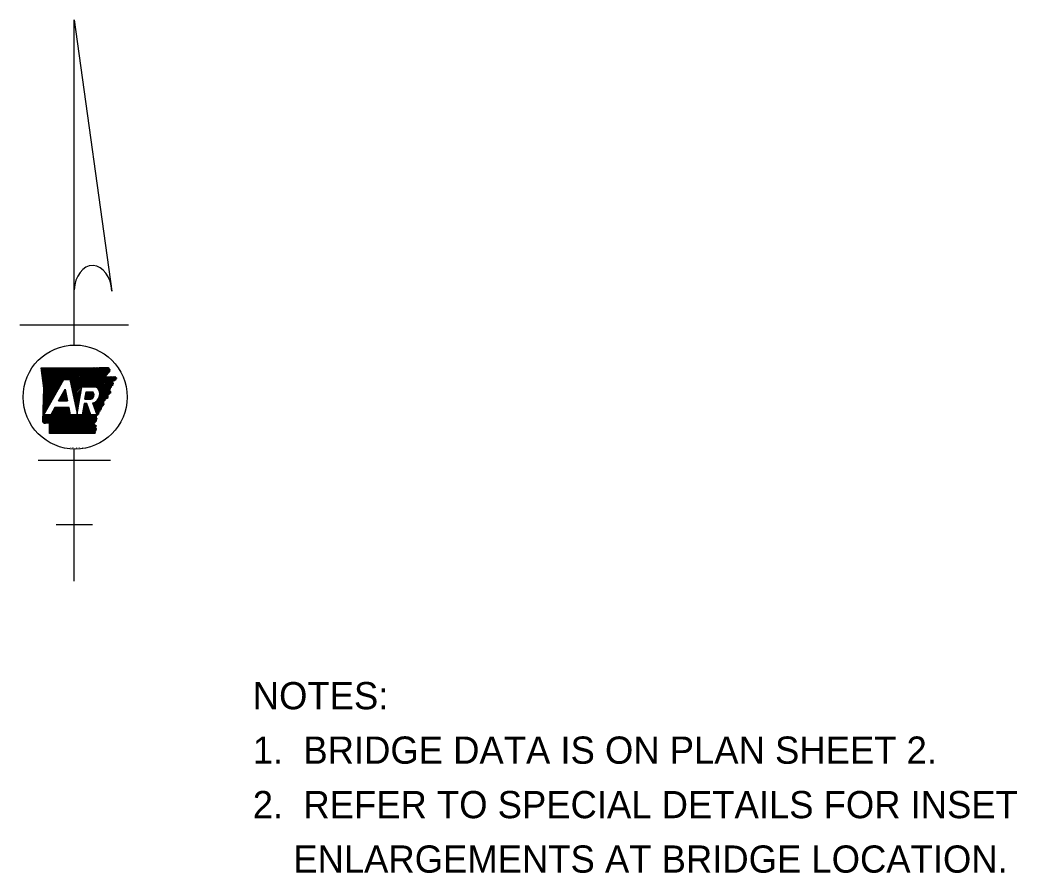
# Model space of a CAD drawing. Extents: x -35254 to 17396, y -8913 to 11592.
# Drawn here: x -7186 to -2354, y -2282 to 1853 of the extents above; entities that cross this region are included whole.
import ezdxf

# ---------------------------------------------------------------- set-up
doc = ezdxf.new("R2010")
doc.units = 0
doc.layers.add('3', color=7, linetype='Continuous')
doc.layers.add('R_Annotation', color=7, linetype='Continuous')

msp = doc.modelspace()

# ---------------------------------------------------------------- linework, layer by layer
at = {"layer": 'R_Annotation'}
for p, q in [((-6922.6, 1853.5), (-6740.7, 539.3)), ((-6922.6, 277.6), (-6922.6, 1853.5)), ((-7185.8, 375), (-6659.5, 375)), ((-7082.2, 164.7), (-7080.1, 166.9)), ((-7081.5, 158.5), (-7073.1, 166.9)), ((-7080.7, 152.3), (-7066.1, 166.9)), ((-7079.9, 146.1), (-7059.2, 166.9)), ((-7079.1, 139.9), (-7052.2, 166.9)), ((-7078.4, 133.7), (-7045.2, 166.9)), ((-7077.6, 127.5), (-7038.3, 166.9)), ((-7076.8, 121.3), (-7031.3, 166.8)), ((-7076.1, 115.2), (-7024.4, 166.8)), ((-7075.3, 109), (-7017.4, 166.8)), ((-7074.5, 102.8), (-7010.4, 166.8)), ((-7073.7, 96.6), (-7003.5, 166.8)), ((-7073, 90.4), (-6996.5, 166.8)), ((-7072.2, 84.2), (-6989.6, 166.8)), ((-7072, 14.8), (-6919.8, 167)), ((-7071.7, 22), (-6926.7, 166.9)), ((-7071.5, 29.2), (-6933.7, 166.9)), ((-7071.4, 78), (-6982.6, 166.8)), ((-7071.2, 36.4), (-6940.7, 166.9)), ((-7071, 43.6), (-6947.7, 166.9)), ((-7070.8, 50.8), (-6954.7, 166.9)), ((-7070.7, 71.8), (-6975.6, 166.8)), ((-7070.5, 58), (-6961.6, 166.9)), ((-7070.3, 65.2), (-6968.6, 166.9)), ((-6968.5, 111.2), (-6912.8, 167)), ((-6961.6, 111.2), (-6905.8, 167)), ((-6954.6, 111.2), (-6898.8, 167)), ((-6947.6, 111.2), (-6891.7, 167.2)), ((-6943.3, 108.6), (-6884.6, 167.3)), ((-6942.1, 102.9), (-6877.5, 167.4)), ((-6940.8, 97.1), (-6870.5, 167.5)), ((-6939.6, 91.4), (-6863.4, 167.6)), ((-6938.4, 85.7), (-6856.3, 167.7)), ((-6937.1, 79.9), (-6849.2, 167.8)), ((-6935.9, 74.2), (-6842.2, 167.9)), ((-6934.7, 68.4), (-6835.1, 168)), ((-6933.5, 62.7), (-6828, 168.1)), ((-6932.2, 57), (-6820.9, 168.3)), ((-6931, 51.2), (-6813.9, 168.4)), ((-6929.8, 45.5), (-6806.8, 168.5)), ((-6928.6, 39.7), (-6799.7, 168.6)), ((-6927.3, 34), (-6792.6, 168.8)), ((-6878.9, 75.4), (-6785.4, 168.9)), ((-6872, 75.4), (-6778.3, 169.1)), ((-6865, 75.4), (-6771.2, 169.3)), ((-6858, 75.4), (-6764, 169.4)), ((-6851.1, 75.4), (-6756.9, 169.6)), ((-6844.1, 75.4), (-6755.4, 164.2)), ((-6837.1, 75.4), (-6752, 160.6)), ((-6830.2, 75.4), (-6751.1, 154.5)), ((-7072.2, 7.6), (-6978.2, 101.5)), ((-7069.9, -60.4), (-6972.7, 111.2)), ((-6972.7, 111.2), (-6943.8, 111.2)), ((-6823.2, 75.4), (-6767, 131.7)), ((-6816.9, 74.8), (-6768.4, 123.3)), ((-6813.1, 71.6), (-6761, 123.7)), ((-6809.7, 68.1), (-6753.7, 124.1)), ((-6806.7, 64.1), (-6746.3, 124.4)), ((-6804.1, 59.7), (-6739, 124.8)), ((-6802, 54.9), (-6731.6, 125.2)), ((-6800.4, 49.5), (-6725, 124.9)), ((-6799.4, 43.5), (-6721.8, 121.1)), ((-6799.4, 36.6), (-6738.4, 97.5)), ((-6724.9, 111.1), (-6718.5, 117.4)), ((-7072.9, -14.1), (-7005.5, 53.4)), ((-7072.7, -6.9), (-6996.4, 69.4)), ((-7072.4, 0.3), (-6987.3, 85.5)), ((-6998.4, 7), (-6966.6, 63.1)), ((-6989.8, 22.3), (-6963.5, 48.5)), ((-6980.7, 38.3), (-6964.7, 54.3)), ((-6971.6, 54.4), (-6966, 60)), ((-6926.1, 28.3), (-6886.6, 67.8)), ((-6924.9, 22.5), (-6888, 59.4)), ((-6923.6, 16.8), (-6889.5, 50.9)), ((-6885.2, 75.4), (-6817.8, 75.4)), ((-6870.6, 14.6), (-6833.9, 51.2)), ((-6869.1, 23), (-6840.9, 51.2)), ((-6867.7, 31.4), (-6847.8, 51.2)), ((-6866.2, 39.8), (-6854.8, 51.2)), ((-6864.7, 48.3), (-6861.8, 51.2)), ((-6864.2, 51.2), (-6832.5, 51.2)), ((-6829.6, -14.5), (-6752.4, 62.7)), ((-6827.7, -19.6), (-6751.1, 57)), ((-6825.8, -24.7), (-6749.8, 51.4)), ((-6806.9, 15.1), (-6753.7, 68.4)), ((-6800.8, 28.2), (-6737.6, 91.4)), ((-6745.4, 76.6), (-6736.8, 85.2)), ((-7073.6, -35.7), (-7032.8, 5.2)), ((-7073.4, -28.5), (-7023.7, 21.2)), ((-7073.2, -21.3), (-7014.6, 37.3)), ((-6998.4, 7), (-6954.6, 7)), ((-6998.1, 7), (-6962.3, 42.8)), ((-6991.1, 7), (-6961.1, 37)), ((-6984.1, 7), (-6959.8, 31.3)), ((-6977.2, 7), (-6958.6, 25.6)), ((-6970.2, 7), (-6957.4, 19.8)), ((-6963.2, 7), (-6956.1, 14.1)), ((-6956.3, 7), (-6954.9, 8.4)), ((-6922.4, 11.1), (-6891, 42.5)), ((-6921.2, 5.3), (-6892.4, 34.1)), ((-6920, -0.4), (-6893.9, 25.6)), ((-6918.7, -6.2), (-6895.4, 17.2)), ((-6917.5, -11.9), (-6896.9, 8.7)), ((-6916.3, -17.6), (-6898.3, 0.3)), ((-6870.6, 14.6), (-6841.7, 14.6)), ((-6863.6, 14.6), (-6830, 48.1)), ((-6856.6, 14.6), (-6827.7, 43.5)), ((-6849.7, 14.6), (-6826.4, 37.8)), ((-6842.7, 14.6), (-6827, 30.3)), ((-6831.5, -9.4), (-6818.2, 3.8)), ((-6823.9, -29.8), (-6748.5, 45.7)), ((-6822.1, -34.9), (-6780.3, 6.9)), ((-6772.3, 14.9), (-6762.5, 24.7)), ((-7074.4, -57.3), (-7060, -43)), ((-7074.1, -50.1), (-7051, -26.9)), ((-7073.9, -42.9), (-7041.9, -10.9)), ((-7072.8, -97.6), (-6999.6, -24.4)), ((-7068.7, -100.4), (-6992.7, -24.4)), ((-7063.7, -102.4), (-6985.7, -24.4)), ((-7055.4, -101.1), (-6978.7, -24.4)), ((-7048.4, -100.9), (-6971.8, -24.4)), ((-7042.9, -102.5), (-6964.8, -24.4)), ((-7042.7, -109.2), (-6957.8, -24.4)), ((-7042.6, -116.1), (-6950.9, -24.4)), ((-7042.6, -123.1), (-6947.2, -27.7)), ((-7042.6, -130), (-6946, -33.4)), ((-7042.6, -137), (-6944.7, -39.1)), ((-7042.6, -143.9), (-6943.5, -44.9)), ((-7016.2, -24.4), (-7036.6, -60.4)), ((-7028.7, -46.4), (-7006.6, -24.4)), ((-7019.6, -30.4), (-7013.6, -24.4)), ((-6947.9, -24.4), (-7016.2, -24.4)), ((-6972.9, -150.9), (-6853.1, -31.1)), ((-6966, -150.9), (-6851.2, -36.2)), ((-6959, -150.9), (-6849.3, -41.3)), ((-6952.1, -150.9), (-6847.5, -46.3)), ((-6915, -23.4), (-6899.8, -8.1)), ((-6913.8, -29.1), (-6901.3, -16.6)), ((-6912.6, -34.8), (-6902.7, -25)), ((-6911.4, -40.6), (-6904.2, -33.4)), ((-6910.1, -46.3), (-6905.7, -41.9)), ((-6882.4, -53.5), (-6855, -26)), ((-6881, -45), (-6856.9, -20.9)), ((-6879.5, -36.6), (-6858.7, -15.8)), ((-6878, -28.2), (-6860.6, -10.7)), ((-6876.6, -19.7), (-6862.6, -5.8)), ((-6875.1, -11.3), (-6869.6, -5.8)), ((-6862.4, -5.8), (-6874.1, -5.8)), ((-6842.3, -60.4), (-6862.4, -5.8)), ((-6833.9, -2.9), (-6812.6, -60.4)), ((-6833.3, -4.4), (-6831.2, -2.2)), ((-6820.2, -40), (-6781.1, -0.8)), ((-6818.3, -45), (-6781.8, -8.6)), ((-6816.4, -50.1), (-6795.1, -28.8)), ((-6814.5, -55.2), (-6798, -38.7)), ((-7075.4, -93.2), (-7042.6, -60.4)), ((-7075.3, -86.1), (-7049.6, -60.4)), ((-7075.1, -78.9), (-7056.5, -60.4)), ((-7074.8, -71.7), (-7063.5, -60.4)), ((-7074.6, -64.5), (-7069.1, -59)), ((-7036.6, -60.4), (-7069.9, -60.4)), ((-7042.5, -150.8), (-6942.3, -50.6)), ((-7035.5, -150.8), (-6941.1, -56.4)), ((-7028.5, -150.8), (-6938.1, -60.4)), ((-7021.6, -150.8), (-6931.2, -60.4)), ((-7014.6, -150.8), (-6924.2, -60.4)), ((-7007.7, -150.8), (-6917.2, -60.4)), ((-7000.7, -150.8), (-6910.3, -60.4)), ((-6993.8, -150.9), (-6903.3, -60.4)), ((-6986.8, -150.9), (-6896.3, -60.4)), ((-6979.9, -150.9), (-6889.4, -60.4)), ((-6945.1, -150.9), (-6845.6, -51.4)), ((-6883.7, -60.4), (-6940.2, -60.4)), ((-6938.1, -150.9), (-6843.7, -56.5)), ((-6931.2, -151), (-6840.6, -60.4)), ((-6924.2, -151), (-6833.6, -60.4)), ((-6917.3, -151), (-6826.7, -60.4)), ((-6910.3, -151), (-6819.7, -60.4)), ((-6908.9, -52.1), (-6907.2, -50.3)), ((-6903.4, -151), (-6817.4, -65)), ((-6896.4, -151), (-6817.1, -71.7)), ((-6889.5, -151), (-6816.7, -78.3)), ((-6882.5, -151), (-6816.4, -85)), ((-6812.6, -60.4), (-6842.3, -60.4)), ((-6875.6, -151.1), (-6827.9, -103.4)), ((-6868.6, -151.1), (-6825.7, -108.2)), ((-6861.6, -151.1), (-6823.6, -113)), ((-6854.7, -151.1), (-6821.4, -117.8)), ((-6847.7, -151.1), (-6819.3, -122.6)), ((-6840.8, -151.1), (-6817.5, -127.8)), ((-6833.8, -151.1), (-6820.6, -137.9)), ((-6826.9, -151.1), (-6823.8, -148)), ((-6922.6, -866.1), (-6922.6, -226.5)), ((-7098, -280.9), (-6747.1, -280.9)), ((-7010.3, -592.4), (-6834.9, -592.4))]:
    msp.add_line(p, q, dxfattribs=at)
for points in [[(-7082.5, 166.8), (-6986.4, 166.8), (-6902, 167), (-6802.6, 168.5), (-6756.5, 169.6)], [(-7082.5, 166.9), (-6986.4, 166.8), (-6902.1, 167), (-6802.6, 168.5), (-6756.5, 169.6)], [(-7075.5, -93.1), (-7070.2, 68.1), (-7082.5, 166.9)], [(-7071.9, 17.5), (-7070.2, 68.1), (-7082.5, 166.8)], [(-6943.8, 111.2), (-6908.1, -55.8), (-6885.2, 75.4)], [(-6726.3, 125.5), (-6717.9, 116.8), (-6738.7, 99.7), (-6736.4, 82.5), (-6754.2, 70.8), (-6748.1, 44.3), (-6761.8, 31.8), (-6763.1, 18.2), (-6779.7, 12.2), (-6782.3, -13.4), (-6794.3, -26.2), (-6800.1, -45.5), (-6817.5, -61.5), (-6816.2, -89.7), (-6828.1, -103), (-6817.3, -127.1), (-6824.7, -151.1)], [(-6770.7, 123.2), (-6725.6, 125.5)], [(-6770.7, 123.2), (-6725.6, 125.5)], [(-6966.6, 63.1), (-6954.6, 7)], [(-6870.6, 14.6), (-6864.2, 51.2)], [(-7075.5, -93.1), (-7071.9, 17.5)], [(-6940.2, -60.4), (-6947.9, -24.4)], [(-6874.1, -5.8), (-6883.7, -60.4)], [(-6824.8, -151.2), (-7042.6, -150.8), (-7042.7, -102.7)], [(-6824.7, -151.1), (-7042.6, -150.8), (-7042.7, -102.7)]]:
    msp.add_lwpolyline(points, dxfattribs=at)
for centre, major_axis, ratio, start_param, end_param in [((-6831.7, 536.5), (-3.9, 126.3), 0.719778, 4.712385, 7.768526), ((-6848.6, 35.8), (-22.3, 0), 0.999987, 1.887169, 3.90762), ((-6842.8, 39.8), (-43.6, 0), 0.999987, 1.777838, 4.099264)]:
    msp.add_ellipse(centre, major_axis=major_axis, ratio=ratio, start_param=start_param, end_param=end_param, dxfattribs=at)
msp.add_ellipse((-6918.5, 25.5), major_axis=(252.1, 0), ratio=0.999976, dxfattribs=at)
for points in [[(-6756.5, 169.6), (-6756.2, 167), (-6755.4, 165.6), (-6755.2, 163.1), (-6754.2, 162), (-6752.4, 161), (-6751, 159.3), (-6750.6, 157.3), (-6751.1, 155.2), (-6751.2, 152.8), (-6751.4, 150.8), (-6751.8, 149), (-6753.2, 147.5), (-6754.5, 146.4), (-6755.8, 145.2), (-6756.7, 143.9), (-6758.2, 142.5), (-6759.8, 141), (-6761.1, 139.7), (-6762.3, 138), (-6762.9, 136.2), (-6764.2, 134.8), (-6765.3, 133.6), (-6766.7, 132), (-6767.4, 130.5), (-6768.8, 128.6), (-6769.1, 126.8), (-6770, 125.4), (-6770.1, 125.2)], [(-6756.5, 169.6), (-6756.2, 167), (-6755.3, 165.6), (-6755.2, 163.1), (-6754.2, 162.1), (-6752.5, 161), (-6750.9, 159.3), (-6750.6, 157.2), (-6751, 155.2), (-6751.2, 152.9), (-6751.4, 150.8), (-6751.8, 149), (-6753.2, 147.5), (-6754.6, 146.4), (-6755.8, 145.2), (-6756.7, 143.9), (-6758.2, 142.5), (-6759.8, 141), (-6761, 139.7), (-6762.3, 138), (-6762.9, 136.2), (-6764.2, 134.8), (-6765.3, 133.7), (-6766.7, 132.1), (-6767.5, 130.4), (-6768.8, 128.6), (-6769.1, 126.8), (-6770, 125.4), (-6770.1, 125.2)], [(-6726.3, 125.5), (-6725.6, 125.5), (-6723.6, 123.4), (-6722.7, 121.6), (-6721.4, 120.6), (-6719.9, 120.1), (-6718.8, 118.7), (-6718, 117.2), (-6718.4, 115.9), (-6720.1, 115.8), (-6721.9, 115.5), (-6723.7, 115.5), (-6725.2, 114.3), (-6723.8, 112.7), (-6722.1, 111.2), (-6721.6, 109.6), (-6722.6, 108.1), (-6724.5, 107.3), (-6726.3, 106.5), (-6728, 105.1), (-6728.8, 103.8), (-6730.6, 103.2), (-6732.5, 102.6), (-6734.2, 102.5), (-6736.1, 102.1), (-6737.9, 101.2), (-6738.7, 99.7), (-6738.4, 97.5), (-6738.5, 95.2), (-6736.6, 94.4), (-6734.8, 94.3), (-6733.1, 93.4), (-6733.4, 92.1), (-6734.6, 90.4), (-6736.1, 89.1), (-6737.5, 88.5), (-6738.9, 87.2), (-6738.4, 86), (-6737.2, 85.2), (-6736.3, 83.8), (-6736.4, 82.6), (-6737.9, 81.7), (-6739.4, 82), (-6740.6, 83.5), (-6741.8, 84), (-6743, 84.5), (-6744.3, 83.8), (-6744.3, 82), (-6744.7, 80.2), (-6744.3, 78.8), (-6743.8, 76.9), (-6743.9, 75.5), (-6744.3, 73.4), (-6745.4, 71.4), (-6746.5, 70.7), (-6747.1, 73), (-6747.2, 74.8), (-6748, 75.9), (-6748.9, 75.9), (-6750.2, 75.1), (-6751.5, 73.7), (-6753.2, 72.2), (-6754.3, 70.7), (-6753.7, 68.9), (-6752.4, 68.4), (-6751.4, 68.7), (-6750.9, 70), (-6749.9, 70.1), (-6748.9, 68.3)], [(-6748.9, 68.3), (-6748.7, 66.6), (-6749.7, 64.7), (-6750.1, 62.9), (-6749.9, 61), (-6751.8, 60), (-6753.4, 58.8), (-6752.4, 57.4), (-6750.7, 56.1), (-6748.9, 55.1), (-6747.8, 54.1), (-6747.5, 51.7), (-6747.2, 50.1), (-6746.6, 47.9), (-6746.4, 46.5), (-6747.4, 44.7), (-6748.7, 44.3), (-6750, 44.7), (-6751.5, 44.9), (-6752.8, 43.7), (-6753.7, 42), (-6754.5, 40.3), (-6755.2, 38.9), (-6755.9, 37.4), (-6757.2, 35.6), (-6758.8, 35.3), (-6760.7, 34.8), (-6761.8, 33.5), (-6761.6, 31.3), (-6760.5, 29.9), (-6759.7, 28), (-6759.1, 26.4), (-6759.4, 24.4), (-6760.2, 22.9), (-6761.3, 22), (-6761.8, 20.1), (-6762.6, 18.6), (-6763.3, 18.2), (-6764.7, 18.3), (-6766.3, 18.6), (-6767.6, 18.5), (-6768.8, 17.8), (-6770.1, 18.2), (-6771.4, 19.7), (-6772.5, 20.7), (-6773.7, 21.1), (-6774.9, 20.5), (-6775.1, 18.5), (-6774.5, 16.5), (-6774, 13.8), (-6774.5, 12.1), (-6774.7, 9.4)], [(-6774.7, 9.4), (-6776.8, 7.8), (-6777.7, 6.2), (-6783, 6.6), (-6782.9, 4.8), (-6784.7, 3.8), (-6786.4, 2.6), (-6785.5, 1.2), (-6783.7, -0.1), (-6781.9, -1.1), (-6780.8, -2.1), (-6780.5, -4.6), (-6780.2, -6.1), (-6779.6, -8.3), (-6779.3, -9.8), (-6780.4, -11.5), (-6781.7, -11.9), (-6782.9, -11.5), (-6784.5, -11.4), (-6785.7, -12.5), (-6786.6, -14.2), (-6787.5, -15.9), (-6788.2, -17.3), (-6788.9, -18.9), (-6790.1, -20.7), (-6791.7, -20.9), (-6793.6, -21.4), (-6794.8, -22.7), (-6794.6, -24.9), (-6793.5, -26.4), (-6792.7, -28.3), (-6792.1, -29.9), (-6792.4, -31.9), (-6793.2, -33.4), (-6794.3, -34.3), (-6794.8, -36.2), (-6795.6, -37.6), (-6796.3, -38.1), (-6797.7, -37.9), (-6799.2, -37.6), (-6800.5, -37.8), (-6801.8, -38.4), (-6803, -38), (-6804.3, -36.6), (-6805.4, -35.5), (-6806.6, -35.1), (-6807.9, -35.7), (-6808.1, -37.7), (-6807.5, -39.7), (-6806.9, -42.5), (-6807.5, -44.1), (-6807.7, -46.9)], [(-6807.7, -46.9), (-6807.8, -47), (-6808.9, -48.3), (-6808.3, -50.4), (-6806, -51.2), (-6804.9, -53.2), (-6804.9, -55), (-6805.6, -57.5), (-6806.7, -58.6), (-6808.7, -59.1), (-6810.3, -59.4), (-6810.6, -62.1), (-6811.3, -63.5), (-6812.6, -63.9), (-6814.3, -63), (-6815.4, -62.5), (-6816.7, -62), (-6818.4, -61), (-6819.7, -61.2), (-6819.3, -63.8), (-6819.2, -63.9), (-6817.7, -65.8), (-6816.3, -67.4), (-6815.7, -69.2)], [(-6807.7, -46.9), (-6807.8, -47), (-6808.9, -48.3), (-6808.3, -50.4), (-6806, -51.2), (-6804.9, -53.2), (-6804.9, -55), (-6805.6, -57.5), (-6806.7, -58.6), (-6808.7, -59.1), (-6810.3, -59.4), (-6810.6, -62.1), (-6811.3, -63.5), (-6812.6, -63.9), (-6814.3, -63), (-6815.4, -62.5), (-6816.7, -62), (-6818.4, -61), (-6819.7, -61.2), (-6819.3, -63.8), (-6819.2, -63.9), (-6817.7, -65.8), (-6816.3, -67.4), (-6815.7, -69.2)], [(-7042.7, -102.7), (-7042.4, -102.8), (-7043.6, -102), (-7045.1, -101.3), (-7046.9, -101.2), (-7049.1, -100.9), (-7050.9, -100.7), (-7052.8, -99.4), (-7054.8, -100.7), (-7057, -101.7), (-7058.4, -100.6), (-7060.1, -101.3), (-7061.3, -100.9), (-7063.3, -102.4), (-7065.3, -101.9), (-7066.7, -102.3), (-7068.5, -102.2), (-7068.9, -100.2), (-7070.6, -99.9), (-7072.1, -99.1), (-7073.1, -97), (-7073.8, -95.4), (-7075.5, -93.1)], [(-7042.7, -102.7), (-7042.4, -102.8), (-7043.6, -102), (-7045.1, -101.3), (-7046.8, -101.2), (-7049, -100.9), (-7050.9, -100.7), (-7052.8, -99.4), (-7054.8, -100.7), (-7057.1, -101.7), (-7058.4, -100.6), (-7060.1, -101.3), (-7061.3, -101), (-7063.4, -102.4), (-7065.3, -101.9), (-7066.7, -102.3), (-7068.5, -102.2), (-7068.9, -100.2), (-7070.6, -99.9), (-7072.1, -99.1), (-7073.1, -97), (-7073.8, -95.4), (-7075.5, -93.1)], [(-6815.7, -69.2), (-6816.2, -70.6), (-6816.9, -73), (-6816.7, -75), (-6815.8, -76.7), (-6814.4, -77.7), (-6812.8, -79), (-6813, -81.1), (-6813.9, -81.9), (-6816, -81.4), (-6817.6, -80.6), (-6818.9, -81.1), (-6820.7, -81.9), (-6822.1, -82.2), (-6822.1, -85), (-6820.3, -87), (-6818.7, -87), (-6816.8, -87.2), (-6816.1, -89.4), (-6817.2, -91.2), (-6819, -92.1), (-6821.2, -91), (-6822.8, -89.8), (-6824.4, -88.8), (-6826.4, -88.3), (-6827.6, -88.5), (-6828.1, -91), (-6827.2, -93.2), (-6825.7, -94.8), (-6824.2, -96.8), (-6824.4, -98.3), (-6825.5, -98.7), (-6827.4, -99.1), (-6828.5, -99.7), (-6828.8, -100.2), (-6828.2, -102.2), (-6827.7, -104.4), (-6827.7, -106.1), (-6828.4, -107.6), (-6829.4, -110), (-6829.3, -111.5), (-6828.5, -112.3), (-6827.7, -112), (-6826.4, -111.2), (-6825.7, -110.2), (-6825, -109), (-6823.8, -108.1), (-6822.3, -108.9), (-6821.9, -110.8), (-6822.8, -112.4), (-6824, -113.1), (-6825.6, -113.7), (-6826.7, -115), (-6826.4, -116.6), (-6825.5, -117.4), (-6823.3, -117), (-6821.9, -116.3), (-6821, -115.5), (-6820, -114.5), (-6819.5, -113.4), (-6818.7, -112.4), (-6817.3, -112.1), (-6816.7, -113), (-6816.9, -115), (-6817.7, -116.9), (-6818.9, -118.5), (-6820.1, -119.6), (-6821.7, -122.1), (-6821.3, -124.3), (-6820.7, -126.2), (-6820, -127.6), (-6818.5, -127.3), (-6816.9, -127.1), (-6816, -127.9), (-6816.1, -129.6), (-6817.2, -131.2), (-6818.4, -132.7), (-6819, -134.8), (-6818.7, -136.4), (-6818.7, -137.7), (-6819.2, -139.2), (-6820, -140), (-6822.3, -140), (-6824.6, -139.7), (-6825.8, -140.4), (-6825.6, -142.5), (-6824.2, -143.9), (-6823.3, -144.7), (-6821.9, -146.4), (-6821.3, -147.7), (-6821.5, -148.9), (-6822.3, -150), (-6824.8, -151.2)], [(-6815.7, -69.2), (-6816.2, -70.6), (-6816.9, -73), (-6816.7, -75), (-6815.8, -76.7), (-6814.4, -77.7), (-6812.8, -79), (-6813, -81.1), (-6813.9, -81.9), (-6816, -81.4), (-6817.6, -80.6), (-6818.9, -81.1), (-6820.7, -81.9), (-6822.1, -82.2), (-6822.1, -85), (-6820.3, -87), (-6818.7, -87), (-6816.8, -87.2), (-6816.1, -89.4), (-6817.2, -91.2), (-6819, -92.1), (-6821.2, -91), (-6822.8, -89.8), (-6824.4, -88.8), (-6826.4, -88.3), (-6827.6, -88.5), (-6828.1, -91), (-6827.2, -93.2), (-6825.7, -94.8), (-6824.2, -96.8), (-6824.4, -98.3), (-6825.5, -98.7), (-6827.4, -99.1), (-6828.5, -99.7), (-6828.8, -100.2), (-6828.2, -102.2), (-6827.7, -104.4), (-6827.7, -106.1), (-6828.4, -107.6), (-6829.4, -110), (-6829.3, -111.5), (-6828.5, -112.3), (-6827.7, -112), (-6826.4, -111.2), (-6825.7, -110.2), (-6825, -109), (-6823.8, -108.1), (-6822.3, -108.9), (-6821.9, -110.8), (-6822.8, -112.4), (-6824, -113.1), (-6825.6, -113.7), (-6826.7, -115), (-6826.4, -116.6), (-6825.5, -117.4), (-6823.3, -117), (-6821.9, -116.3), (-6821, -115.5), (-6820, -114.5), (-6819.5, -113.4), (-6818.7, -112.4), (-6817.3, -112.1), (-6816.7, -113), (-6816.9, -115), (-6817.7, -116.9), (-6818.9, -118.5), (-6820.1, -119.6), (-6821.7, -122.1), (-6821.3, -124.3), (-6820.7, -126.2), (-6820, -127.6), (-6818.5, -127.3), (-6816.9, -127.1), (-6816, -127.9), (-6816.1, -129.6), (-6817.2, -131.2), (-6818.4, -132.7), (-6819, -134.8), (-6818.7, -136.4), (-6818.7, -137.7), (-6819.2, -139.2), (-6820, -140), (-6822.3, -140), (-6824.6, -139.7), (-6825.8, -140.4), (-6825.6, -142.5), (-6824.2, -143.9), (-6823.3, -144.7), (-6821.9, -146.4), (-6821.3, -147.7), (-6821.5, -148.9), (-6822.3, -150), (-6824.8, -151.2)]]:
    msp.add_spline(points, degree=3, dxfattribs=at)

# ---------------------------------------------------------------- texts
at = {"layer": '3'}
for s, p in [('NOTES:  ', (-6057.6, -1487.8)), ('1.  BRIDGE DATA IS ON PLAN SHEET 2.', (-6057.6, -1751.8)), ('2.  REFER TO SPECIAL DETAILS FOR INSET', (-6057.6, -2015.8)), ('    ENLARGEMENTS AT BRIDGE LOCATION.', (-6057.6, -2279.8))]:
    msp.add_text(s, height=132, dxfattribs=at).set_placement(p)
at = {"layer": 'R_Annotation'}
msp.add_text('STS 10-03-17', height=7.288, dxfattribs=at).set_placement((-6942.6, -224.5))

doc.saveas('drawing.dxf')
